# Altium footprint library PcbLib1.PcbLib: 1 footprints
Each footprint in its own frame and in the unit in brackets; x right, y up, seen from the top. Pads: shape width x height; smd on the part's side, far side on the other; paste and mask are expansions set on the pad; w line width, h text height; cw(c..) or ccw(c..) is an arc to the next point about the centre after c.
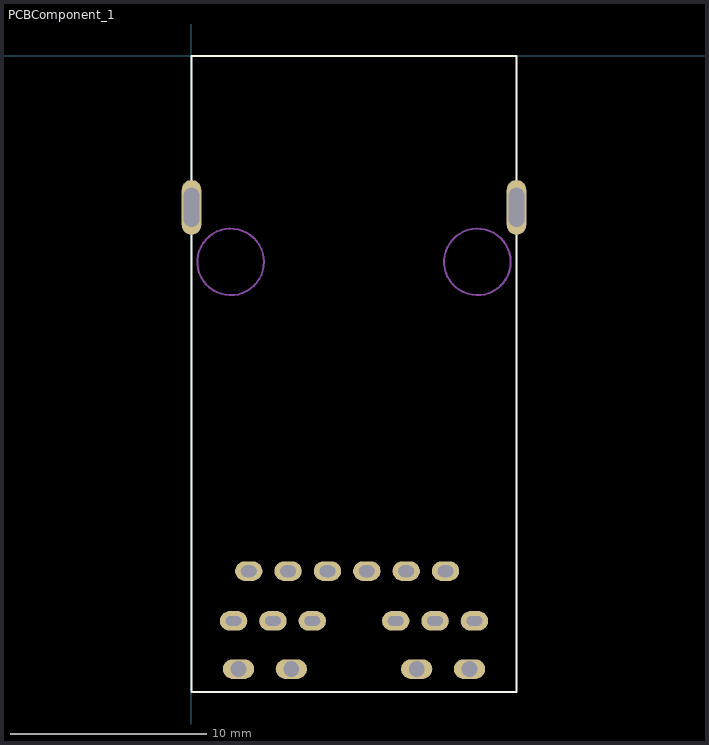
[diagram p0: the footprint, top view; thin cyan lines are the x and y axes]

## PCBComponent_1 [mm]
pads (18):
  oval 1x2.8 hole 0.8 slot 2 at 90 deg mask+0.01: ""(0,-7.74) ""(16.6,-7.74)
  oval 1.4x1 hole 0.5 slot 0.8 at 0 deg mask+0.01: ""(2.15,-28.86) ""(4.16,-28.86) ""(6.17,-28.86) ""(10.43,-28.86) ""(12.44,-28.86) ""(14.45,-28.86)
  oval 1.6x1 hole 0.8 mask+0.01: ""(2.4,-31.32) ""(5.1,-31.32) ""(11.5,-31.32) ""(14.2,-31.32)
  oval 1.4x1 hole 0.6 slot 0.8 at 0 deg mask+0.01: ""(2.925,-26.32) ""(4.935,-26.32) ""(6.945,-26.32) ""(8.955,-26.32) ""(10.965,-26.32) ""(12.975,-26.32)
Top Overlay:
  lines w0.1: 0,-32.5 16.6,-32.5 16.6,0 0,0 0,-32.5
Mechanical 1:
  circle w0.1: c2,-10.525 r1.7
  circle w0.1: c14.6,-10.525 r1.7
